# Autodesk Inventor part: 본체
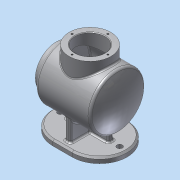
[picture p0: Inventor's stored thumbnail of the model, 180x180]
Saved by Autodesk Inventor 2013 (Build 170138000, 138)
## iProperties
Created: 2016-04
Part Number: 본체
Material: 알루미늄 6061
Document SubType Name: Modeling
Designer: dgall
Mass: 908.835 g
Surface Area: 1225.22 cm^2
Volume: 335.364 cm^3
Density: 2.71 g/cm^3
Author: dgall
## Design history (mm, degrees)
sketch "스케치1"
  geometry: L1 (0, 0)-(120, 0); L2 (-2, 38)-(10, 38); L3 (10, 38)-(10, 50); L4 (10, 50)-(109.087, 50); L5 (-2, 27)-(13, 27); L6 (13, 27)-(13, 47); L7 (13, 47)-(107.145, 47); L8 (-2, 27)-(-2, 38); A1 r 120 centre (0, 0) between (120, 0) and (109.087, 50); A2 r 117 centre (0, 0) between (117, 0) and (107.145, 47); 1 further point
  constraints: 16 end point, 4 point on circle, 2 centre point, 2 coincident, 2 parallel, 2 perpendicular, 1 horizontal, 1 point on line
  dimensions: "d12" = 120 radius of A1; "d14" = 3 radial gap between concentric circles of A1 A2; "d15" = 3 distance between parallel lines of L6 L3; "d16" = 3 distance between parallel lines of L7 L4; "d17" = 12 distance of L2.start L2.end; "d18" = 110 distance from line of L1.end L3; "d19" = 76 diameter of L2 L1; "d20" = 54 diameter of L5 L1; "d21" = 100 diameter of L4 L1
revolve "회전1" sketch "스케치1" stored, may be unused: angle "d22" = 90 deg
node "작업 평면2"
  node "작업 평면1"
sketch "스케치2"
  geometry: L1 (6, 50)-(105.087, 50) reference; L2 (105.087, -50)-(105.087, 50) reference; C1 r 38 at (55.544, 0); 3 further points
  constraints: 2 midpoint, 1 centre point, 1 horizontal alignment, 1 vertical alignment
  dimensions: "d25" = 76 diameter of C1
extrude "돌출1" join sketch "스케치2" stored distance "d27" = 10; taper "d28" = 0 deg
sketch "스케치3"
  geometry: C1 r 38 at (0, 0) reference; C2 r 27 at (0, 0); 1 further point
  constraints: 1 centre point, 1 coincident
  dimensions: "d29" = 54 diameter of C2
extrude "돌출2" cut sketch "스케치3" stored distance "d31" = 10; taper "d32" = 0 deg
node "작업축2"
node "작업 평면4"
  node "작업 평면3"
sketch "스케치4"
  geometry: L1 (-111.087, 50)-(-111.087, -50) reference; L2 (-12, 50)-(-12, -50) reference; L3 (-12, 50)-(-111.087, 50) reference; L4 (-12, 50)-(-12, -50) reference; L5 (0, 38)-(0, -38) reference; L6 (-12, -50)-(-111.087, -50) reference; L7 (-79.044, 50)-(-44.044, 50); L8 (-79.044, -50)-(-44.044, -50); C1 r 27 at (-61.544, 0) reference; A1 r 120 centre (-2, 0) between (-111.087, 50) and (-111.087, -50) reference; A2 r 50 centre (-44.044, 0) between (-44.044, -50) and (-44.044, 50); A3 r 50 centre (-79.044, 0) between (-79.044, 50) and (-79.044, -50); 4 further points
  constraints: 4 end point, 4 horizontal alignment, 4 point on circle, 4 point on line, 3 vertical alignment, 2 centre point, 2 collinear, 2 midpoint, 2 tangent, 1 other
  dimensions: "d35" = 50 radius of A2; "d37" = 50 radius of A3; "d38" = 135 dimension on A2 A3
extrude "돌출3" join sketch "스케치4" distance "d39" = 10; taper "d40" = 0 deg
node "작업 평면5"
node "작업 평면6"
node "작업 평면8"
  node "작업 평면7"
sketch "스케치5"
  geometry: L1 (50, -69)-(-50, -69) reference; L2 (-40, -26)-(-40, -69); L3 (-40, -69)-(0, -69); L4 (0, -69)-(0, -48.558); L5 (0, -48.558)-(-20.419, -45.024); L6 (-20.419, -45.024)-(-36.021, -33.202); L7 (-36.021, -33.202)-(-40, -26); C1 r 50 at (0, 0) reference; 1 further point
  constraints: 12 end point, 2 perpendicular, 1 midpoint, 1 point on line
  dimensions: "d44" = 40 distance from line of L2 point (0, 0); "d45" = 43 distance of L2.start L2.end; "d46" = 7.20213 vertical distance of L6.end L2.start; "d47" = 3.97936 horizontal distance of L6.end L2.start; "d48" = 11.82177 vertical distance of L5.end L6.end; "d49" = 15.60142 horizontal distance of L5.end L6.end; "d50" = 3.53413 vertical distance of L4.end L5.end
extrude "돌출4" join sketch "스케치5" stored distance "d51" = 10; taper "d52" = 0 deg
node "작업 평면9"
node "작업 평면10"
sketch "스케치6"
  geometry: L1 (0, 0)-(10, 0) reference; L2 (0, -39)-(0, 0) reference; L3 (10, -39)-(0, -39) reference; L4 (10, 0)-(10, -39) reference; L5 (-56, -8)-(-56, 68) reference; L6 (0, -39)-(10, -39) reference; L7 (-11.956, -39)-(-61.956, -39) reference; L8 (-34.456, -39)-(-30.788, -18.194); L9 (-11.956, -49)-(23.044, -49) reference; L10 (-34.456, -39)-(0, -39); L11 (0, -39)-(0, -18.194); L12 (-30.788, -18.194)-(0, -18.194); 4 further points
  constraints: 8 end point, 3 midpoint, 2 point on line, 1 coincident, 1 parallel, 1 perpendicular
  dimensions: "d60" = 40 horizontal distance of point (5.544, -49) L8.start; "d62" = 100 deg angle of L8 L7; "d64" = 20.80609 vertical distance of L8.start L8.end
extrude "돌출5" join sketch "스케치6" stored distance "d65" = 10; taper "d66" = 0 deg
node "작업 평면11"
fillet "모깎기1" dims "d67" = 5
fillet "모깎기2" dims "d68" = 2
chamfer "모따기1" distance "d69" = 1; stored, may be unused: second distance "d70" = 2, angle "d71" = 45 deg
fillet "모깎기3" dims "d72" = 3
chamfer "모따기2" distance "d73" = 3; stored, may be unused: second distance "d74" = 2, angle "d75" = 45 deg
sketch "스케치7" dims "d76" = 65
  geometry: L1 (0, 0)-(32.5, 0); C1 r 28 at (0, 0) reference; 1 further point
  constraints: 2 end point, 1 coincident, 1 horizontal, 1 horizontal alignment, 2 other
hole "구멍1" sketch "스케치7" at (32.5, 0) diameter "d78" = 3.242; stored, may be unused: countersink angle "d82" = 90 deg, drill point angle "d84" = 118 deg; dims "d79" = 8, "d80" = 4, "d81" = 2, "d83" = 10
sketch "스케치8" dims "d88" = 65
  geometry: L1 (0, 0)-(32.5, 0); C1 r 38 at (0, 0) reference; C2 r 28 at (0, 0) reference
  constraints: 2 end point, 1 coincident, 1 horizontal, 1 horizontal alignment, 2 other
hole "구멍2" sketch "스케치8" at (32.5, 0) diameter "d90" = 3.242; stored, may be unused: countersink angle "d94" = 90 deg, drill point angle "d96" = 118 deg; dims "d91" = 8, "d92" = 4, "d93" = 2, "d95" = 10
sketch "스케치9"
  geometry: L1 (100.456, -5)-(66, -5) reference; L2 (66, -5)-(66, -40) reference; L3 (66, -40)-(56, -40) reference; L4 (56, -40)-(56, -5) reference; L5 (56, -5)-(21.544, -5) reference; L6 (21.544, -5)-(21.544, 5) reference; L7 (21.544, 5)-(56, 5) reference; L8 (56, 5)-(56, 40) reference; L9 (56, 40)-(66, 40) reference; L10 (66, 40)-(66, 5) reference; L11 (66, 5)-(100.456, 5) reference; L12 (100.456, 5)-(100.456, -5) reference; L13 (44.044, 47)-(79.044, 47) reference; L14 (79.044, -47)-(44.044, -47) reference; L15 (44.044, 50)-(79.044, 50) reference; L16 (79.044, -50)-(44.044, -50) reference; L17 (79.044, 50)-(44.044, 50) reference; C1 r 5 at (7.544, 0); C2 r 5 at (115.544, 0); A1 r 47 centre (79.044, 0) between (79.044, -47) and (79.044, 47) reference; A2 r 47 centre (44.044, 0) between (44.044, 47) and (44.044, -47) reference; A3 r 47 centre (79.044, 0) between (79.044, -47) and (79.044, 47) reference; A4 r 47 centre (44.044, 0) between (44.044, 47) and (44.044, -47) reference; A5 r 50 centre (79.044, 0) between (79.044, -50) and (79.044, 50) reference; A6 r 50 centre (44.044, 0) between (44.044, 50) and (44.044, -50) reference; 3 further points
  constraints: 2 centre point, 2 horizontal alignment, 2 midpoint, 1 coincident
  dimensions: "d100" = 10 diameter of C1; "d102" = 54 horizontal distance of C1.centre point (61.544, 50); "d103" = 54 horizontal distance of point (61.544, 50) C2.centre; "d104" = 10 diameter of C2
extrude "돌출6" cut sketch "스케치9" distance "d105" = 10; taper "d106" = 0 deg
fillet "모깎기4" dims "d107" = 3
fillet "모깎기5" dims "d108" = 3
fillet "모깎기6" dims "d109" = 3
node "작업 평면12"
node "솔리드1"
mirror "대칭1"
mirror "대칭2"
pattern_circular "원형 패턴1" dims angle "d86" = 360 deg
pattern_circular "원형 패턴2" dims angle "d98" = 360 deg
node "작업축1"
node "투영된 루프1"
node "투영된 루프2"
node "투영된 루프3"
node "투영된 루프4"
node "투영된 루프5"
node "투영된 루프6"
node "투영된 루프7"
other parameters: "d23" = 0, "d24" = 65, "d33" = 0, "d34" = 79, "d41" = 0, "d42" = 0, "d43" = -61
